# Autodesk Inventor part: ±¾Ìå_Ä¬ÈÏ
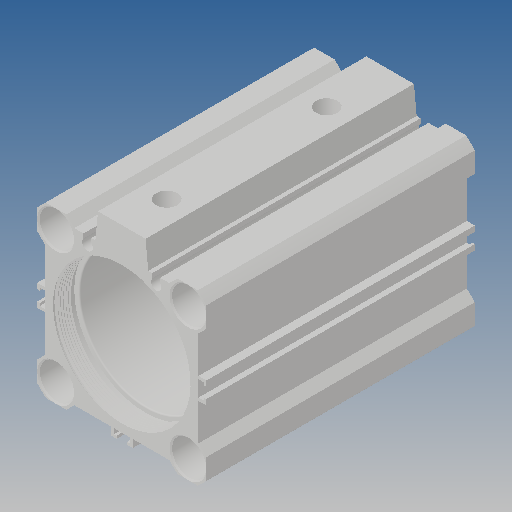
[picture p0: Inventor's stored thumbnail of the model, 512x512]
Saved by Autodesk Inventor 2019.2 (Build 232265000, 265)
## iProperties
Created: 2012-03
Part Number: ±¾Ìå_Ä¬ÈÏ
Material: Ogólny
Document SubType Name: Modeling
Designer: CADENGINEERING4
Density: 1 g/cm^3
Appearance: Domyślna
Author: CADENGINEERING4
Revision Number: ÈÎºÎ
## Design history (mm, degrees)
feature "NONE"
node "Bryła1"
